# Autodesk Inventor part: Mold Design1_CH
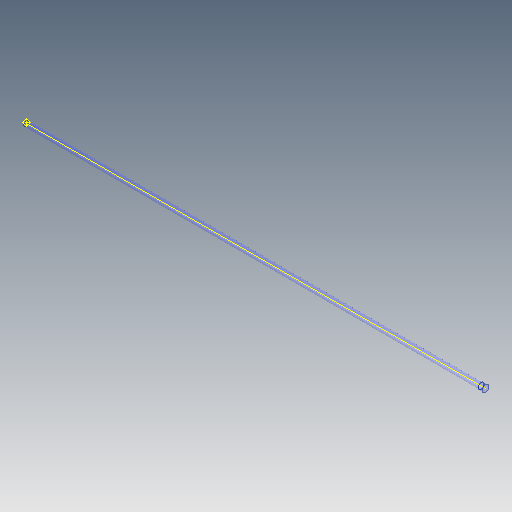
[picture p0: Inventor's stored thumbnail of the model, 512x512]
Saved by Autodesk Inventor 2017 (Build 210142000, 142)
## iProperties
Created: 2016-07
Part Number: Mold Design1_CH
Material: Generic
Document SubType Name: Modeling
Designer: Sandeep
Density: 1 g/cm^3
Appearance: Clear - Blue
Author: Sandeep
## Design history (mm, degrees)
workplane "Work Plane1"
node "Cooling Segment1"
  sketch "Sketch1"
    geometry: L1 (0, 0)-(0, -5.178); L2 (0, -5.178)-(6.924, -4.745); L3 (6.924, -4.745)-(6.924, -4); L4 (6.924, -4)-(700, -4); L5 (700, -4)-(700, 0); L6 (0, 0)-(700, 0)
    constraints: 12 end point, 3 perpendicular, 1 parallel
    dimensions: "d0" = 4 distance between parallel lines of L4 L6 (derived); "d1" = 6.924 distance between parallel lines of L3 L1 (derived); "d2" = 93.58 deg angle of L2 L3; "d3" = 0.7445 distance of L2.end L3.end (derived)
  workpoint "Work Point1"
  workaxis "Work Axis1"
body "Solid1"
revolve "Revolution1" stored, may be unused: angle "d4" = 0 deg
body "Srf1"
feature "RevolutionSrf1" dims angle "d5" = 0 deg
